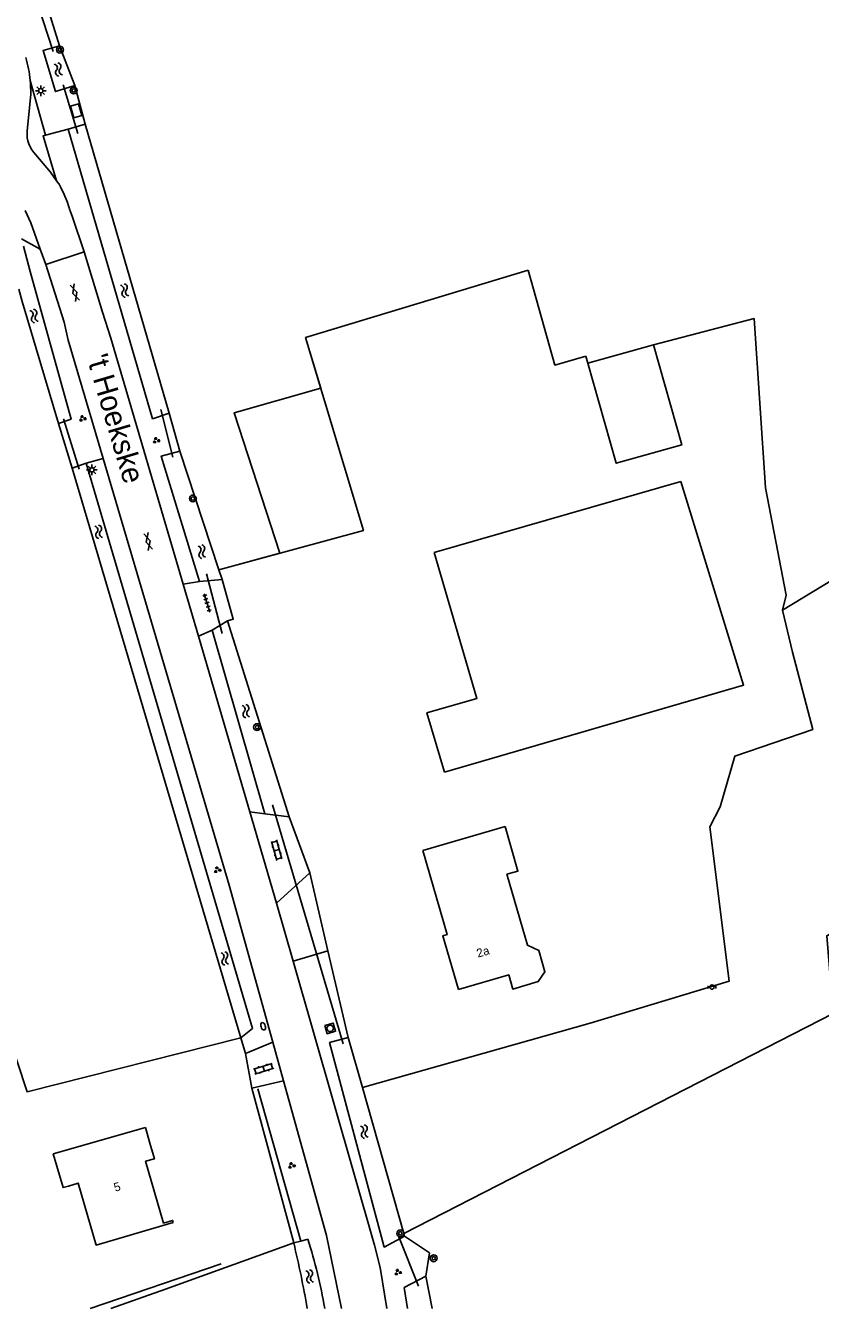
# Model space of a CAD drawing. Extents: x 136000 to 141000, y 400494 to 402006.
# Drawn here: x 137420.8 to 137513.3, y 400500 to 400649.5 of the extents above; entities that cross this region are included whole.
import ezdxf

# ---------------------------------------------------------------- set-up
doc = ezdxf.new("R2010")
doc.units = 0
for name, color, linetype in [('gg-afsc-draadraster', 7, 'Continuous'), ('gg-afsc-erfafscheiding', 7, 'Continuous'), ('gg-afsc-lijn draadraster', 7, 'Continuous'), ('gg-anno-huisnummerreeks BGT', 7, 'Continuous'), ('gg-anno-openbare ruimte label', 7, 'Continuous'), ('gg-bbg-bijgebouw', 7, 'Continuous'), ('gg-bbg-gedigitaliseerde bebouwing', 7, 'Continuous'), ('gg-bbg-gedigitaliseerde bijgebouw', 7, 'Continuous'), ('gg-bbg-hoofdgebouw', 7, 'Continuous'), ('gg-bbg-lage trafo', 7, 'Continuous'), ('gg-bbg-open loods', 7, 'Continuous'), ('gg-knt-bronhoudergrens', 7, 'Continuous'), ('gg-knt-verharding', 7, 'Continuous'), ('gg-kntw-bovenkant insteek waterloop', 7, 'Continuous'), ('gg-kntw-midden sloot', 7, 'Continuous'), ('gg-kwrk-duiker nz buis', 7, 'Continuous'), ('gt-grn-groengrens', 7, 'Continuous'), ('gt-symb-boom', 7, 'Continuous'), ('gt-symb-brandkraan', 7, 'Continuous'), ('gt-symb-gesloten verharding', 7, 'Continuous'), ('gt-symb-groenvak', 7, 'Continuous'), ('gt-symb-klinker verharding', 7, 'Continuous'), ('gt-symb-lichtmast', 7, 'Continuous'), ('gt-symb-peilbuis', 7, 'Continuous'), ('gt-symb-rioolschacht', 7, 'Continuous'), ('gt-symb-tegel verharding', 7, 'Continuous'), ('gt-symb-watersymbool', 7, 'Continuous')]:
    doc.layers.add(name, color=color, linetype=linetype)

# ---------------------------------------------------------------- blocks, each defined once
blk = doc.blocks.new('gt0-BOOM')
at = {"layer": 'gt-symb-boom'}
for radius in [0.4, 0.2]:
    blk.add_circle((0, 0), radius, dxfattribs=at)
blk = doc.blocks.new('gt0-PBUIS')
at = {"layer": 'gt-symb-peilbuis'}
blk.add_circle((0, 0), 0.25, dxfattribs=at)
for centre, start, end in [((-0.21, 0), 141.9073, 218.0927), ((0.21, 0), 321.9073, 38.0927)]:
    blk.add_arc(centre, 0.243, start, end, dxfattribs=at)
blk = doc.blocks.new('gt0-WA')
at = {"layer": 'gt-symb-watersymbool'}
for centre, start, end in [((-0.32, 0.02), 28.0725, 151.9275), ((0.43, 0.42), 208.0725, 331.9275), ((-0.32, -0.43), 28.0725, 151.9275), ((0.43, -0.03), 208.0725, 331.9275)]:
    blk.add_arc(centre, 0.425, start, end, dxfattribs=at)
blk = doc.blocks.new('gt0-GRVAK')
at = {"layer": 'gt-symb-groenvak'}
for p, q in [((-0.11, 0.19), (-0.23, 0.24)), ((-0.18, 0.15), (0.09, 0.15)), ((-0.09, 0.21), (-0.16, 0.32)), ((-0.05, 0.21), (-0.05, 0.39)), ((0, 0.21), (0.06, 0.32)), ((0.02, 0.19), (0.13, 0.24)), ((0.26, -0.05), (0.2, 0.06)), ((0.3, -0.05), (0.3, 0.13)), ((0.35, -0.05), (0.41, 0.06)), ((-0.24, -0.23), (-0.36, -0.18)), ((-0.32, -0.26), (-0.05, -0.26)), ((-0.23, -0.21), (-0.29, -0.09)), ((-0.18, -0.2), (-0.18, -0.02)), ((-0.14, -0.21), (-0.07, -0.09)), ((-0.12, -0.23), (0, -0.18)), ((0.24, -0.07), (0.12, -0.02)), ((0.17, -0.11), (0.44, -0.11)), ((0.37, -0.07), (0.49, -0.02))]:
    blk.add_line(p, q, dxfattribs=at)
blk = doc.blocks.new('gt0-RS')
at = {"layer": 'gt-symb-rioolschacht'}
blk.add_lwpolyline([(-0.5, -0.5), (0.5, -0.5), (0.5, 0.5), (-0.5, 0.5)], close=True, dxfattribs=at)
blk.add_circle((0, 0), 0.375, dxfattribs=at)
blk = doc.blocks.new('gt0-TEG1')
at = {"layer": 'gt-symb-tegel verharding'}
for p, q in [((-1.12, 0), (1.12, 0)), ((-0.9, -0.25), (-0.9, 0.25)), ((-0.45, -0.25), (-0.45, 0.25)), ((0, -0.25), (0, 0.25)), ((0.45, -0.25), (0.45, 0.25)), ((0.9, -0.25), (0.9, 0.25))]:
    blk.add_line(p, q, dxfattribs=at)
blk = doc.blocks.new('gt0-GESVH1')
at = {"layer": 'gt-symb-gesloten verharding'}
for p, q in [((-0.99, -0.26), (0.01, 0.24)), ((0.01, -0.26), (-0.99, 0.24)), ((0.01, 0.24), (1.01, -0.26)), ((1.01, 0.24), (0.01, -0.26))]:
    blk.add_line(p, q, dxfattribs=at)
blk = doc.blocks.new('gt0-LMAST')
at = {"layer": 'gt-symb-lichtmast'}
for p, q in [((-0.18, 0.17), (-0.45, 0.44)), ((-0.01, 0.25), (-0.01, 0.62)), ((0.17, 0.17), (0.44, 0.44)), ((-0.26, 0), (-0.63, 0)), ((-0.18, -0.18), (-0.45, -0.45)), ((-0.01, -0.25), (-0.01, -0.63)), ((0.44, -0.45), (0.17, -0.18)), ((0.24, 0), (0.62, 0))]:
    blk.add_line(p, q, dxfattribs=at)
blk.add_circle((-0.01, 0), 0.25, dxfattribs=at)
blk = doc.blocks.new('gt0-KL1')
at = {"layer": 'gt-symb-klinker verharding'}
for p, q in [((-1.15, 0.3), (1.15, 0.3)), ((-1, -0.3), (-1, 0.3)), ((-0.5, 0.3), (-0.5, 0.45)), ((0, -0.3), (0, 0.3)), ((0.5, 0.3), (0.5, 0.45)), ((1, -0.3), (1, 0.3)), ((-1.15, -0.3), (1.15, -0.3)), ((-0.5, -0.45), (-0.5, -0.3)), ((0.5, -0.45), (0.5, -0.3))]:
    blk.add_line(p, q, dxfattribs=at)
blk = doc.blocks.new('gt0-BR')
at = {"layer": 'gt-symb-brandkraan'}
for centre, radius, start, end in [((-0.24, 0), 0.206, 107.5669, 252.4331), ((0.6, -2.66), 3, 106.892, 107.5669), ((0, -0.69), 0.938, 73.108, 106.892), ((-0.6, -2.66), 3, 72.4331, 73.108), ((0.24, 0), 0.206, 287.567, 72.4331), ((0.6, 2.66), 3, 252.4331, 253.108), ((0, 0.69), 0.938, 253.108, 286.8921), ((-0.6, 2.66), 3, 286.8921, 287.567)]:
    blk.add_arc(centre, radius, start, end, dxfattribs=at)

msp = doc.modelspace()

# ---------------------------------------------------------------- linework, layer by layer
at = {"layer": 'gg-afsc-draadraster'}
for p, q in [((137486.02, 400610.96), (137486.27, 400610.16)), ((137508.94, 400581.39), (137510.09, 400576.46))]:
    msp.add_line(p, q, dxfattribs=at)
for points in [[(137698.29, 400646.42), (137674.69, 400677.68), (137673.39, 400679.41), (137563.8, 400614.68), (137508.94, 400581.39)], [(137479.29, 400620.99), (137482.43, 400609.93), (137486.02, 400610.96)], [(137493.9, 400612.3), (137505.63, 400615.35), (137506.97, 400595.65), (137509.35, 400583.14), (137508.94, 400581.39)], [(137501.67, 400558.47), (137503.38, 400564.36), (137512.45, 400567.48), (137510.09, 400576.46)], [(137464.83, 400508.73), (137514.83, 400534.36), (137514.1, 400543.42), (137569.44, 400573.9)], [(137501.67, 400558.47), (137500.48, 400556.12), (137502.72, 400538.13), (137486.53, 400533.22), (137460, 400525.74)]]:
    msp.add_lwpolyline(points, dxfattribs=at)
at = {"layer": 'gg-afsc-erfafscheiding'}
for p, q in [((137426.52, 400642.51), (137427.7, 400638.02)), ((137426.21, 400597.94), (137424.6, 400603.15)), ((137437.48, 400604.32), (137438.74, 400599.9)), ((137453.87, 400550.75), (137455.99, 400541.65)), ((137455.99, 400541.65), (137458.33, 400531.58)), ((137446.38, 400529.72), (137445.84, 400531.51)), ((137452.01, 400507.62), (137447.12, 400525.68)), ((137464.92, 400508.41), (137467.83, 400506.48)), ((137467.83, 400506.48), (137467.38, 400503.75))]:
    msp.add_line(p, q, dxfattribs=at)
at = {"layer": 'gg-afsc-lijn draadraster'}
for p, q in [((137486.02, 400610.96), (137486.27, 400610.16)), ((137508.94, 400581.39), (137510.09, 400576.46))]:
    msp.add_line(p, q, dxfattribs=at)
for points in [[(137698.29, 400646.42), (137674.69, 400677.68), (137673.39, 400679.41), (137563.8, 400614.68), (137508.94, 400581.39)], [(137443.29, 400586.09), (137460.12, 400590.66), (137453.39, 400613.14), (137479.29, 400620.99)], [(137479.29, 400620.99), (137482.43, 400609.93), (137486.02, 400610.96)], [(137493.9, 400612.3), (137505.63, 400615.35), (137506.97, 400595.65), (137509.35, 400583.14), (137508.94, 400581.39)], [(137501.67, 400558.47), (137503.38, 400564.36), (137512.45, 400567.48), (137510.09, 400576.46)], [(137501.67, 400558.47), (137500.48, 400556.12), (137502.72, 400538.13), (137486.53, 400533.22), (137460, 400525.74)]]:
    msp.add_lwpolyline(points, dxfattribs=at)
at = {"layer": 'gg-bbg-bijgebouw'}
msp.add_line((137468.35, 400588.09), (137497.1, 400596.39), dxfattribs=at)
msp.add_lwpolyline([(137469.57, 400562.48), (137467.51, 400569.39), (137473.34, 400571.06), (137468.35, 400588.09)], dxfattribs=at)
at = {"layer": 'gg-bbg-gedigitaliseerde bebouwing'}
msp.add_line((137467.02, 400553.36), (137476.61, 400556.16), dxfattribs=at)
for points in [[(137476.61, 400556.16), (137478.12, 400550.97), (137476.82, 400550.59)], [(137423.98, 400518.01), (137425.13, 400514.07), (137425.75, 400514.25), (137426.89, 400514.59), (137428.99, 400507.38), (137437.96, 400509.99)]]:
    msp.add_lwpolyline(points, dxfattribs=at)
at = {"layer": 'gg-bbg-gedigitaliseerde bijgebouw'}
msp.add_lwpolyline([(137497.1, 400596.39), (137504.4, 400572.65), (137469.57, 400562.48)], dxfattribs=at)
at = {"layer": 'gg-bbg-hoofdgebouw'}
msp.add_line((137434.72, 400521.09), (137423.98, 400518.01), dxfattribs=at)
for points in [[(137471.2, 400537.15), (137469.37, 400543.42), (137469.86, 400543.56), (137467.02, 400553.36)], [(137471.2, 400537.15), (137477.05, 400538.86), (137477.52, 400537.22), (137480.48, 400538.08), (137481.26, 400539.24), (137480.54, 400541.71), (137479.23, 400542.33), (137476.82, 400550.59)], [(137437.96, 400509.99), (137437.88, 400510.24), (137436.84, 400509.94), (137434.74, 400517.14), (137435.78, 400517.44), (137435.25, 400519.27), (137434.72, 400521.09)]]:
    msp.add_lwpolyline(points, dxfattribs=at)
at = {"layer": 'gg-bbg-lage trafo'}
msp.add_lwpolyline([(137425.99, 400640.1), (137426.94, 400640.38), (137427.33, 400639.03), (137426.39, 400638.75), (137425.99, 400640.1)], dxfattribs=at)
at = {"layer": 'gg-bbg-open loods'}
msp.add_line((137486.27, 400610.16), (137493.9, 400612.3), dxfattribs=at)
msp.add_lwpolyline([(137493.9, 400612.3), (137497.2, 400600.64), (137489.57, 400598.5), (137486.27, 400610.16)], dxfattribs=at)
at = {"layer": 'gg-knt-bronhoudergrens'}
msp.add_line((137423.29, 400651.78), (137424.71, 400647.13), dxfattribs=at)
for points in [[(137443.29, 400586.09), (137450.4, 400588.02), (137445.07, 400604.39), (137455.15, 400607.24), (137453.39, 400613.14), (137479.29, 400620.99)], [(137445.84, 400531.51), (137420.94, 400525.24), (137416.15, 400539.74), (137361.14, 400522.9), (137366.65, 400502.62), (137366.85, 400501.89)], [(137430.69, 400500), (137437.08, 400502.22), (137452.01, 400507.62)]]:
    msp.add_lwpolyline(points, dxfattribs=at)
at = {"layer": 'gg-knt-verharding'}
for p, q in [((137421.36, 400641.52), (137420.94, 400637.22)), ((137424.38, 400631.43), (137424.63, 400631.08)), ((137423.13, 400621.65), (137422.48, 400623.45)), ((137427.58, 400623.15), (137423.13, 400621.65)), ((137427.58, 400623.15), (137429.72, 400616.09)), ((137423.13, 400621.65), (137425.27, 400614.94)), ((137439.12, 400584.42), (137441.03, 400584.72)), ((137439.12, 400584.42), (137440.9, 400578.34)), ((137443.68, 400584.94), (137441.03, 400584.72)), ((137444.28, 400580.12), (137442.48, 400579.04)), ((137440.9, 400578.34), (137442.48, 400579.04)), ((137440.9, 400578.34), (137446.9, 400557.86)), ((137446.9, 400557.86), (137450, 400547.21)), ((137446.9, 400557.86), (137448.64, 400557.64)), ((137451.48, 400557.28), (137448.64, 400557.64)), ((137453.87, 400550.75), (137451.48, 400557.28)), ((137450, 400547.21), (137453.87, 400550.75)), ((137450, 400547.21), (137451.94, 400540.45)), ((137446.38, 400529.72), (137449.55, 400531.01)), ((137449.55, 400531.01), (137450.8, 400526.52)), ((137447.12, 400525.68), (137446.38, 400529.72)), ((137450.8, 400526.52), (137447.12, 400525.68)), ((137450.8, 400526.52), (137455.8, 400508.49)), ((137455.8, 400508.49), (137457.55, 400500)), ((137462.08, 400504.75), (137462.84, 400500))]:
    msp.add_line(p, q, dxfattribs=at)
for points in [[(137421.97, 400634.44), (137423.66, 400632.43), (137424.38, 400631.43)], [(137422.48, 400623.45), (137421.37, 400626.53), (137420.73, 400627.97)], [(137427.58, 400623.15), (137426.18, 400627.31), (137425.9, 400628.13)], [(137439.12, 400584.42), (137430.71, 400613.09), (137429.72, 400616.09)], [(137425.27, 400614.94), (137425.73, 400612.85), (137429.79, 400599.07)], [(137429.79, 400599.07), (137444.46, 400549.33), (137449.55, 400531.01)], [(137444.28, 400580.12), (137444.96, 400580.34), (137443.68, 400584.94)], [(137451.94, 400540.45), (137461.41, 400507.37), (137462.08, 400504.75)]]:
    msp.add_lwpolyline(points, dxfattribs=at)
for centre, radius, start, end in [((137407.24, 400641.79), 14.12, 5.4023, 16.5191), ((137407.36, 400641.8), 14, 358.8693, 5.4259), ((137424.33, 400636.89), 3.4, 174.5727, 226.0951), ((137411.67, 400623.78), 14.87, 17.029, 29.4291)]:
    msp.add_arc(centre, radius, start, end, dxfattribs=at)
at = {"layer": 'gg-kntw-bovenkant insteek waterloop'}
for p, q in [((137424.71, 400647.13), (137426.52, 400642.51)), ((137427.7, 400638.02), (137425.72, 400637.45)), ((137427.7, 400638.02), (137437.48, 400604.32)), ((137438.74, 400599.9), (137443.29, 400586.09)), ((137427.82, 400598.49), (137426.21, 400597.94)), ((137445.84, 400531.51), (137426.21, 400597.94)), ((137443.29, 400586.09), (137443.68, 400584.94)), ((137444.28, 400580.12), (137451.48, 400557.28)), ((137442.48, 400579.04), (137448.64, 400557.64)), ((137458.33, 400531.58), (137460, 400525.74)), ((137460, 400525.74), (137464.83, 400508.73)), ((137452.01, 400507.62), (137452.82, 400507.84)), ((137452.82, 400507.84), (137453.66, 400508.06)), ((137464.83, 400508.73), (137464.92, 400508.41)), ((137464.85, 400502.44), (137467.38, 400503.75)), ((137467.38, 400503.75), (137468.13, 400500)), ((137464.85, 400502.44), (137465.27, 400500))]:
    msp.add_line(p, q, dxfattribs=at)
for points in [[(137426.52, 400642.51), (137424.24, 400641.82), (137422.81, 400646.61), (137424.71, 400647.13)], [(137425.72, 400637.45), (137435.56, 400603.69), (137437.48, 400604.32)], [(137420.54, 400623.79), (137421.28, 400620.84), (137426.06, 400603.62), (137424.6, 400603.15)], [(137419.99, 400618.77), (137420.38, 400617.34), (137424.6, 400603.15)], [(137441.03, 400584.72), (137436.57, 400599.33), (137438.74, 400599.9)], [(137445.84, 400531.51), (137447.2, 400532.62), (137427.82, 400598.49)], [(137464.92, 400508.41), (137462.55, 400507.15), (137456.17, 400530.97), (137458.33, 400531.58)]]:
    msp.add_lwpolyline(points, dxfattribs=at)
for centre, radius, start, end in [((137339.36, 400480.5), 115.86, 9.6895, 13.5371), ((137388.15, 400487.9), 68.54, 10.1679, 17.1073)]:
    msp.add_arc(centre, radius, start, end, dxfattribs=at)
at = {"layer": 'gg-kntw-midden sloot'}
for p, q in [((137452.82, 400507.84), (137447.82, 400525.59)), ((137428.29, 400500), (137443.54, 400505.2))]:
    msp.add_line(p, q, dxfattribs=at)
at = {"layer": 'gg-kwrk-duiker nz buis'}
for p, q in [((137423.98, 400646.5), (137422.17, 400652.1)), ((137426.85, 400636.92), (137425.13, 400642.62)), ((137437.92, 400599.21), (137436.53, 400604.78)), ((137426.99, 400597.82), (137425.17, 400603.68)), ((137443.66, 400578.65), (137441.83, 400585.62)), ((137457.75, 400530.82), (137449.51, 400558.7)), ((137466.52, 400502.58), (137464.25, 400508.33))]:
    msp.add_line(p, q, dxfattribs=at)
at = {"layer": 'gt-grn-groengrens'}
for p, q in [((137423.07, 400636.72), (137421.3, 400643.12)), ((137423.07, 400636.72), (137425.72, 400637.45)), ((137422.48, 400623.45), (137420.3, 400624.64)), ((137427.82, 400598.49), (137429.79, 400599.07)), ((137455.99, 400541.65), (137451.94, 400540.45))]:
    msp.add_line(p, q, dxfattribs=at)
msp.add_lwpolyline([(137423.07, 400636.72), (137422.81, 400636.64), (137424.38, 400631.43)], dxfattribs=at)

# ---------------------------------------------------------------- block references
at = {"layer": 'gt-symb-boom'}
for p in [(137424.77, 400646.7), (137426.37, 400641.95), (137440.25, 400594.39), (137447.73, 400567.74), (137464.41, 400508.74), (137468.31, 400505.84)]:
    msp.add_blockref('gt0-BOOM', p, dxfattribs=at)
at = {"layer": 'gt-symb-brandkraan', "rotation": 106.26020470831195}
msp.add_blockref('gt0-BR', (137448.44, 400532.87), dxfattribs=at)
at = {"layer": 'gt-symb-gesloten verharding'}
for p, rotation in [((137426.5, 400618.36), 108.05455246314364), ((137435.05, 400589.39), -74.99108632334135)]:
    msp.add_blockref('gt0-GESVH1', p, dxfattribs=dict(at, rotation=rotation))
at = {"layer": 'gt-symb-groenvak'}
for p in [(137427.39, 400603.72), (137435.97, 400601.16), (137443.09, 400551.11), (137451.74, 400516.65), (137464.12, 400504.2)]:
    msp.add_blockref('gt0-GRVAK', p, dxfattribs=at)
at = {"layer": 'gt-symb-klinker verharding'}
for p, rotation in [((137450.01, 400553.4), -73.73979529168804), ((137448.49, 400527.93), 17.039535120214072)]:
    msp.add_blockref('gt0-KL1', p, dxfattribs=dict(at, rotation=rotation))
at = {"layer": 'gt-symb-lichtmast'}
for p in [(137422.54, 400641.92), (137428.5, 400597.73)]:
    msp.add_blockref('gt0-LMAST', p, dxfattribs=at)
at = {"layer": 'gt-symb-peilbuis'}
msp.add_blockref('gt0-PBUIS', (137500.71, 400537.44), dxfattribs=at)
at = {"layer": 'gt-symb-rioolschacht', "rotation": -73.50377577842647}
msp.add_blockref('gt0-RS', (137456.25, 400532.63), dxfattribs=at)
at = {"layer": 'gt-symb-tegel verharding', "rotation": -73.61369433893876}
msp.add_blockref('gt0-TEG1', (137441.9, 400582.22), dxfattribs=at)
at = {"layer": 'gt-symb-watersymbool'}
for p, rotation in [((137424.59, 400644.34), 111.35437736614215), ((137432.32, 400618.57), 111.35437736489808), ((137421.77, 400615.61), 111.35437736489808), ((137429.29, 400590.45), 107.33010869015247), ((137441.31, 400588.14), 107.33010869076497), ((137446.44, 400569.55), 107.33010869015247), ((137443.99, 400540.72), 107.33010869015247), ((137460.24, 400520.54), 107.33010868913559), ((137453.87, 400503.66), 107.33010869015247)]:
    msp.add_blockref('gt0-WA', p, dxfattribs=dict(at, rotation=rotation))

# ---------------------------------------------------------------- texts
at = {"layer": 'gg-anno-huisnummerreeks BGT'}
for s, p in [('2a', (137473.47, 400540.87)), ('5', (137431.21, 400513.58))]:
    msp.add_text(s, height=1, rotation=16.3, dxfattribs=at).set_placement(p)
at = {"layer": 'gg-anno-openbare ruimte label'}
msp.add_text("'t Hoekske", height=2.5, rotation=286.5, dxfattribs=at).set_placement((137427.87, 400610.79))

doc.saveas('drawing.dxf')
